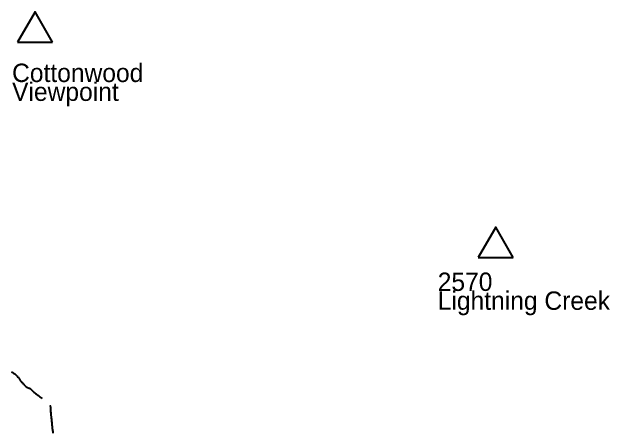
# Model space of a CAD drawing. Extents: x 322505 to 642419, y 5806860 to 5919753.
# Drawn here: x 552397 to 563779, y 5871219 to 5879242 of the extents above; entities that cross this region are included whole.
import ezdxf

# ---------------------------------------------------------------- set-up
doc = ezdxf.new("R2010")
doc.units = 0
doc.header["$LTSCALE"] = 140
for name, color, linetype, lineweight in [('1', 7, 'Continuous', 40), ('2', 7, 'Continuous', 40), ('5', 7, 'Continuous', 40)]:
    doc.layers.add(name, color=color, linetype=linetype, lineweight=lineweight)

msp = doc.modelspace()

# ---------------------------------------------------------------- linework, layer by layer
at = {"layer": '1'}
msp.add_line((561270.6, 5874564.9), (561936, 5874564.9), dxfattribs=at)
msp.add_lwpolyline([(561936, 5874564.9), (561603.3, 5875141.1), (561270.6, 5874564.9)], dxfattribs=at)
at = {"layer": '2'}
msp.add_line((552504.5, 5878665.4), (553169.9, 5878665.4), dxfattribs=at)
msp.add_lwpolyline([(553169.9, 5878665.4), (552837.2, 5879241.6), (552504.5, 5878665.4)], dxfattribs=at)
at = {"layer": '5'}
for points in [[(552386, 5872387), (552400, 5872380), (552410, 5872375), (552417, 5872371), (552422, 5872367), (552429, 5872362), (552439, 5872355), (552450, 5872346), (552462, 5872337), (552467, 5872332), (552473, 5872327), (552479, 5872321), (552484, 5872316), (552490, 5872310), (552498, 5872300), (552505, 5872291), (552513, 5872281), (552520, 5872271), (552527, 5872262), (552533, 5872252), (552540, 5872243), (552547, 5872233), (552555, 5872221), (552565, 5872208), (552573, 5872199), (552580, 5872191), (552587, 5872185), (552593, 5872179), (552598, 5872173), (552607, 5872165), (552616, 5872155), (552626, 5872145), (552635, 5872134), (552644, 5872125), (552650, 5872118), (552656, 5872112), (552663, 5872106), (552670, 5872100), (552680, 5872093), (552687, 5872089), (552693, 5872086), (552700, 5872084), (552706, 5872083), (552711, 5872081), (552721, 5872077), (552731, 5872072), (552741, 5872066), (552750, 5872060), (552759, 5872053), (552765, 5872049), (552770, 5872044), (552775, 5872038), (552781, 5872032), (552788, 5872025), (552801, 5872012), (552813, 5872000), (552825, 5871990), (552836, 5871980), (552847, 5871971), (552858, 5871963), (552869, 5871955), (552880, 5871947), (552892, 5871939), (552902, 5871932), (552916, 5871922), (552928, 5871912), (552941, 5871902), (552955, 5871890), (552973, 5871876)], [(553118, 5871746), (553120, 5871743), (553124, 5871734), (553126, 5871725), (553128, 5871717), (553128, 5871709), (553128, 5871701), (553128, 5871686), (553129, 5871671), (553129, 5871655), (553131, 5871640), (553132, 5871625), (553134, 5871603), (553136, 5871582), (553139, 5871560), (553141, 5871535), (553145, 5871504), (553147, 5871484), (553149, 5871466), (553150, 5871451), (553151, 5871437), (553153, 5871422), (553155, 5871405), (553157, 5871385), (553159, 5871366), (553161, 5871347), (553163, 5871328), (553164, 5871314), (553165, 5871299), (553167, 5871284), (553169, 5871266), (553172, 5871246), (553174, 5871228), (553176, 5871219)]]:
    msp.add_lwpolyline(points, dxfattribs=at)

# ---------------------------------------------------------------- texts
at = {"layer": '1'}
for s, p in [('2570', (560500.4, 5873926.6)), ('Lightning Creek', (560500.4, 5873566.6))]:
    msp.add_text(s, height=350, dxfattribs=at).set_placement(p)
at = {"layer": '2'}
for s, p in [('Cottonwood', (552399.5, 5877906.7)), ('Viewpoint', (552399.5, 5877546.7))]:
    msp.add_text(s, height=350, dxfattribs=at).set_placement(p)

doc.saveas('drawing.dxf')
